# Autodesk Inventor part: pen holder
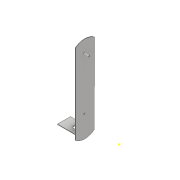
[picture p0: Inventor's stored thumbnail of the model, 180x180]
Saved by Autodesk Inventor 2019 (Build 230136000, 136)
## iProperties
Created: 2020-02
Part Number: pen holder
Material: Generic
Document SubType Name: Modeling
Designer: Krupashree
Density: 1 g/cm^3
Appearance: Default
Author: Krupashree
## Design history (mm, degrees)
sketch "Sketch1"
  geometry: L1 (42.11, 17.644)-(10.24, 17.644); L2 (42.11, 10.115)-(10.24, 10.267); A1 r 6.288 centre (37.073, 13.88) between (42.11, 10.115) and (42.11, 17.644); A2 r 5.898 centre (14.843, 13.955) between (10.24, 17.644) and (10.24, 10.267); 1 further point
  constraints: 4 end point, 4 point on circle, 2 centre point
extrude "Extrusion1" new body sketch "Sketch1" distance "d0" = 0.2; taper "d1" = 0 deg
sketch "Sketch2"
  geometry: L1 (11.506, 11.087)-(16.648, 11.087); L2 (16.648, 11.087)-(16.648, 11.309); L3 (16.648, 11.309)-(11.506, 11.309); L4 (11.506, 11.309)-(11.506, 11.087); 1 further point
  constraints: 8 end point, 2 parallel, 1 horizontal, 1 perpendicular
extrude "Extrusion2" join sketch "Sketch2" distance "d2" = 8; taper "d3" = 0 deg
sketch "Sketch3"
  geometry: 1 further point
workplane "Work Plane1"
sketch "Sketch4"
  geometry: 1 further point
workplane "Work Plane2"
sketch "Sketch5"
  geometry: C1 r 1.004 at (-3.137, 2.468); 1 further point
  constraints: 1 centre point
extrude "Extrusion3" cut sketch "Sketch5" extent not by distance; stored distance "d5" = 5; taper "d6" = 0 deg
sketch "Sketch6"
  geometry: C1 r 0.25 at (-14.228, 38.562); 1 further point
  constraints: 1 centre point
  dimensions: "d7" = 0.5 diameter of C1
extrude "Extrusion4" join sketch "Sketch6" distance "d8" = 2; taper "d9" = 0 deg
sketch "Sketch7"
  geometry: C1 r 0.25 at (14.228, 17.752); 1 further point
  constraints: 1 centre point
  dimensions: "d10" = 0.5 diameter of C1
extrude "Extrusion5" cut sketch "Sketch7" extent not by distance; stored distance "d11" = 0; taper "d12" = 0 deg
body "Solid1"
other parameters: "d4" = 0
